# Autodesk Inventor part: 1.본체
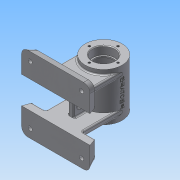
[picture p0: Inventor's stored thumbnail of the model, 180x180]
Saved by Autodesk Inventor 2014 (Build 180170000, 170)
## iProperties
Created: 2016-07
Part Number: 1.본체
Material: 알루미늄 6061
Document SubType Name: Modeling
Designer: 406-8
Density: 2.71 g/cm^3
Appearance: 알루미늄 - 평지
Mass: 497.65 g
Surface Area: 543.556 cm^2
Volume: 183.635 cm^3
Author: 406-8
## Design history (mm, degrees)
sketch "스케치1"
  geometry: L1 (50, -55)-(-50, -55); L2 (-50, -55)-(-50, 55); L3 (-50, 55)-(50, 55); L4 (50, 55)-(50, -55); 1 further point
  constraints: 8 end point, 2 parallel, 1 horizontal, 1 perpendicular
  dimensions: "d0" = 100 distance of L1.start L1.end; "d1" = 50 distance from line of point (0, 0) L4; "d3" = 55 distance from line of L1 point (0, 0); "d4" = 110 distance of L3.end L1.start
extrude "돌출1" new body sketch "스케치1" distance "d5" = 12; taper "d6" = 0 deg
feature "면 기울기1" dims angle "d7" = -20 deg
fillet "모깎기1" dims "d8" = 10
sketch "스케치2"
  geometry: L1 (-40.603, 55)-(40.603, 55) reference; L2 (-50, -45.603)-(-50, 45.603) reference; 2 further points
  dimensions: "d9" = 12.5 distance from line of L1 point (-37.5, 42.5); "d10" = 12.5 distance from line of L2 point (-37.5, 42.5)
hole "구멍1" sketch "스케치2" at (-37.5, 42.5) diameter "d11" = 6; stored, may be unused: countersink angle "d15" = 90 deg, drill point angle "d17" = 118 deg; dims "d12" = 6, "d13" = 10, "d14" = 4, "d16" = 8
sketch "스케치3"
  geometry: C1 r 27 at (0, 70); 1 further point
  constraints: 1 centre point, 1 vertical alignment
  dimensions: "d24" = 54 diameter of C1; "d25" = 70 distance of point (0, 0) C1.centre
extrude "돌출2" join sketch "스케치3" stored distance "d26" = 70; taper "d27" = 0 deg
sketch "스케치4"
  geometry: L1 (30, 20)-(-30, 20); L2 (-30, 20)-(-30, -20); L3 (-30, -20)-(30, -20); L4 (30, -20)-(30, 20); L5 (0, 55)-(12, 50.632) reference; L6 (12, -50.632)-(0, -55) reference; 2 further points
  constraints: 8 end point, 2 parallel, 1 horizontal, 1 midpoint, 1 perpendicular, 1 vertical alignment
  dimensions: "d28" = 35 distance from line of L1 L5.start; "d29" = 35 distance from line of L3 L6.end; "d30" = 60 distance of L2.end L3.end
extrude "돌출3" cut sketch "스케치4" stored distance "d31" = 70; taper "d32" = 0 deg
sketch "스케치5"
  geometry: L1 (-27, 20)-(27, 20); L2 (27, 20)-(27, 28); L3 (27, 28)-(-27, 28); L4 (-27, 28)-(-27, 20); L5 (-50, -20)-(50, -20) reference; L6 (-27, -20)-(27, -20); L7 (27, -20)-(27, -28); L8 (27, -28)-(-27, -28); L9 (-27, -28)-(-27, -20); L10 (50, 20)-(-50, 20) reference; 4 further points
  constraints: 16 end point, 4 midpoint, 4 parallel, 2 horizontal, 2 perpendicular, 2 vertical alignment, 1 point on line
  dimensions: "d33" = 8 distance between parallel lines of L1 L3; "d34" = 8 distance of L8.end L6.start; "d35" = 54 distance of L7.end L8.end; "d36" = 54 distance of L2.end L3.end
extrude "돌출4" join sketch "스케치5" stored distance "d37" = 70; taper "d38" = 0 deg
sketch "스케치6"
  geometry: L1 (12, -20)-(70, -20) reference; L2 (52, 20)-(22, 20); L3 (22, 20)-(22, -20); L4 (22, -20)-(52, -20); L5 (52, -20)-(52, 20); L6 (32, 20)-(32, -20); L7 (43, -35)-(43, 35) reference; L8 (12, 20)-(70, 20) reference; 1 further point
  constraints: 10 end point, 4 point on line, 3 parallel, 1 horizontal, 1 perpendicular
  dimensions: "d39" = 64 diameter of point (0, 0) L6; "d40" = 21 distance between parallel lines of L7 L3; "d41" = 30 distance between parallel lines of L3 L5
extrude "돌출5" join sketch "스케치6" stored distance "d42" = 8; taper "d43" = 0 deg
sketch "스케치7"
  geometry: L1 (-8, 32)-(8, 32); L2 (-8, 28.5)-(8, 28.5); L3 (8, 35.5)-(-8, 35.5); A1 r 3.5 centre (-8, 32) between (-8, 35.5) and (-8, 28.5); A2 r 3.5 centre (8, 32) between (8, 28.5) and (8, 35.5); 2 further points
  constraints: 8 end point, 4 point on circle, 4 tangent, 2 centre point, 1 horizontal, 1 midpoint, 1 parallel, 1 vertical alignment
  dimensions: "d44" = 3.5 radius of A2; "d45" = 32 distance of point (0, 0) point (0, 32); "d46" = 23 dimension on A2 A1
extrude "돌출6" cut sketch "스케치7" stored distance "d47" = 8; taper "d48" = 0 deg
sketch "스케치8"
  geometry: L1 (97, 35)-(43, 35) reference; L2 (70, 35)-(70, -35); L3 (86, 35)-(86, 23); L4 (86, 23)-(84, 23); L5 (84, 23)-(84, 21); L6 (84, 21)-(92, 21); L7 (92, 21)-(92, -21); L8 (92, -21)-(84, -21); L9 (84, -21)-(84, -23); L10 (84, -23)-(86, -23); L11 (86, -23)-(86, -35); L12 (43, -35)-(97, -35) reference; L13 (86, 35)-(70, 35); L14 (86, -35)-(70, -35); 1 further point
  constraints: 24 end point, 6 parallel, 4 perpendicular, 2 collinear, 2 point on line, 1 midpoint
  dimensions: "d49" = 140 diameter of point (0, 0) L2; "d50" = 28 diameter of L9 L2; "d51" = 32 diameter of L11 L2; "d52" = 32 diameter of L3 L2; "d53" = 28 diameter of L5 L2; "d54" = 44 diameter of L7 L2; "d55" = 42 distance of L6.end L7.end; "d56" = 12 distance of L3.start L3.end; "d57" = 12 distance of L10.end L11.end; "d58" = 2 distance of L4.end L5.end
revolve "회전1" sketch "스케치8" stored, may be unused: angle "d59" = 90 deg
sketch "스케치9"
  geometry: C1 r 16 at (0, 0) reference; 2 further points
  constraints: 1 vertical alignment
  dimensions: "d60" = 21 distance of C1.centre point (0, 21)
hole "구멍2" sketch "스케치9" at (0, 21) diameter "d61" = 3.242; stored, may be unused: countersink angle "d65" = 90 deg, drill point angle "d67" = 118 deg; dims "d62" = 8, "d63" = 4, "d64" = 2, "d66" = 10
node "작업 평면1"
sketch "스케치10"
  geometry: L1 (27, 35)-(-27, 35) reference; C1 r 5 at (0, 13); 1 further point
  constraints: 1 centre point, 1 vertical alignment
  dimensions: "d72" = 22 distance from line of L1 C1.centre; "d73" = 10 diameter of C1
extrude "돌출7" join sketch "스케치10" stored distance "d74" = 8; taper "d75" = 0 deg
hole "구멍3" diameter "d78" = 5.188; stored, may be unused: countersink angle "d82" = 90 deg, drill point angle "d84" = 0 deg; dims "d76" = 10, "d77" = 10, "d79" = 20, "d80" = 4, "d81" = 2, "d83" = 20
node "작업 평면2"
sketch "스케치11"
  geometry: L1 (27, 35)-(-27, 35) reference; L2 (27, -35)-(27, 35) reference; 2 further points
  constraints: 1 other
  dimensions: "d85" = 35 distance from line of point (0, 0) L1; "d86" = 27 distance from line of L2 point (0, 0)
feature "엠보싱1" sketch "스케치11" dims "d0" = 100, "d1" = 50, "d3" = 55, "d4" = 110, "d87" = 0.5, "d88" = 0
sketch "스케치12"
  geometry: L1 (0, 70)-(-15.898, 44.559); L2 (0, 70)-(0, 43); 1 further point
  constraints: 4 end point, 1 vertical, 1 vertical alignment, 1 other
  dimensions: "d89" = 32 deg angle of L1 L2; "d90" = 30 distance of L1.start L1.end
node "작업 평면3"
sketch "스케치13"
  geometry: C1 r 6 at (0, 0); 4 further points
  constraints: 1 centre point, 1 coincident
  dimensions: "d91" = 12 diameter of C1
extrude "돌출8" join sketch "스케치13" stored distance "d92" = 8; taper "d93" = 0 deg
hole "구멍4" diameter "d96" = 5.188; stored, may be unused: countersink angle "d100" = 90 deg, drill point angle "d102" = 0 deg; dims "d94" = 10, "d95" = 10, "d97" = 20, "d98" = 4, "d99" = 2, "d101" = 20
fillet "모깎기2" dims "d103" = 2
fillet "모깎기3" dims "d104" = 2
fillet "모깎기4" dims "d105" = 2
fillet "모깎기5" dims "d106" = 0.3
chamfer "모따기1" distance "d107" = 1; stored, may be unused: second distance "d108" = 2, angle "d109" = 45 deg
fillet "모깎기6" dims "d110" = 3
node "솔리드1"
pattern_linear "직사각형 패턴1" dims "d20" = 85, "d23" = 75
pattern_circular "원형 패턴1" dims angle "d69" = 360 deg
mirror "대칭1"
